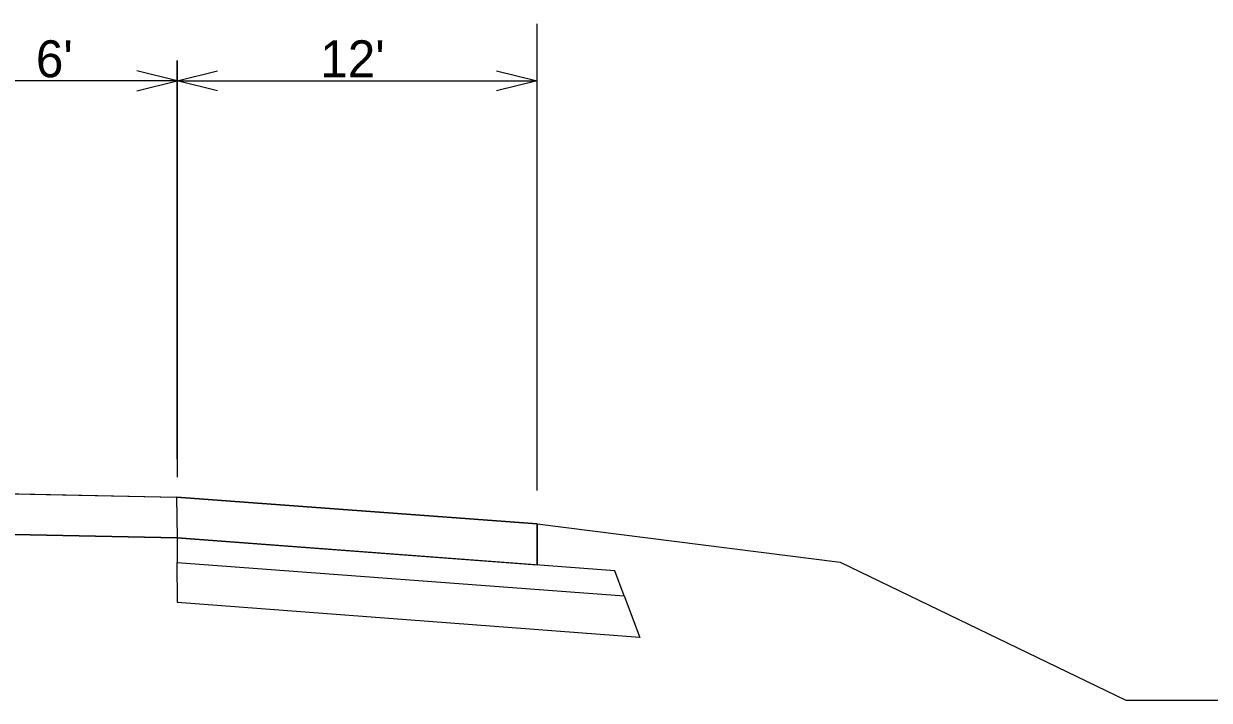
# Model space of a CAD drawing. Extents: x 10133 to 81668, y 4856 to 11018.
# Drawn here: x 11836.4 to 12317.7, y 8656.6 to 8931.3 of the extents above; entities that cross this region are included whole.
import ezdxf

# ---------------------------------------------------------------- set-up
doc = ezdxf.new("R2010")
doc.units = 0
for name, color, linetype in [('dsnStdDimension', 7, 'Continuous'), ('dsnXsPCCPavementBottom', 7, 'Continuous'), ('dsnXsShldrEarthFill', 7, 'Continuous'), ('dsnXsShldrGranular', 7, 'Continuous'), ('dsnXsShldrGranularBottom', 7, 'Continuous'), ('dsnXsShldrSpecialBackBottom', 7, 'Continuous')]:
    doc.layers.add(name, color=color, linetype=linetype)

msp = doc.modelspace()

# ---------------------------------------------------------------- linework, layer by layer
at = {"layer": 'dsnStdDimension'}
for p, q in [((12076.34, 8709.14), (11898.67, 8722.47)), ((11898.67, 8712.57), (12080.17, 8698.96)), ((12080.17, 8698.96), (12076.34, 8709.14))]:
    msp.add_line(p, q, dxfattribs=at)
msp.add_lwpolyline([(11898.67, 8722.47), (11898.67, 8722.47), (11898.67, 8712.57), (11898.67, 8712.57)], dxfattribs=at)
msp.add_lwpolyline([(11898.67, 8712.57), (11898.67, 8712.57), (12080.17, 8698.96), (12086.53, 8682.08), (11898.78, 8696.25), (11898.78, 8696.25)], close=True, dxfattribs=at)
at = {"layer": 'dsnXsPCCPavementBottom'}
for p, q in [((12044.78, 8741.68), (12044.78, 8931.28)), ((11898.67, 8754.52), (11898.67, 8916.39)), ((11898.67, 8916.39), (11898.67, 8754.52)), ((11898.67, 8916.39), (11898.67, 8754.52)), ((11898.67, 8754.52), (11898.67, 8916.39)), ((11898.67, 8916.39), (11898.67, 8747.22)), ((11898.67, 8908.07), (11800.5, 8908.07)), ((11898.67, 8908.07), (12044.78, 8908.07))]:
    msp.add_line(p, q, dxfattribs=at)
for points in [[(11882.28, 8903.97), (11898.67, 8908.07), (11882.28, 8912.17)], [(11915.06, 8903.97), (11898.67, 8908.07), (11915.06, 8912.17)], [(12028.39, 8912.17), (12044.78, 8908.07), (12028.39, 8903.97)]]:
    msp.add_lwpolyline(points, dxfattribs=at)
at = {"layer": 'dsnXsShldrGranular'}
msp.add_line((11898.67, 8722.47), (11699.65, 8726.7), dxfattribs=at)
msp.add_lwpolyline([(11700, 8743.25), (11898.43, 8739.03), (11898.67, 8722.47)], dxfattribs=at)
msp.add_lwpolyline([(12044.78, 8728.14), (11898.43, 8739.03), (11898.67, 8722.47), (12044.78, 8711.51)], close=True, dxfattribs=at)
at = {"layer": 'dsnXsShldrGranularBottom'}
for p, q in [((11700, 8743.25), (11898.43, 8739.03)), ((11898.43, 8739.03), (11898.67, 8722.47)), ((11898.43, 8739.03), (11898.67, 8722.47)), ((11898.43, 8739.03), (11898.67, 8722.47)), ((11898.43, 8739.03), (11898.67, 8722.47)), ((12044.78, 8728.14), (12167.89, 8712.67)), ((11699.65, 8726.7), (11898.67, 8722.47)), ((12167.89, 8712.67), (12283.88, 8656.55)), ((12283.88, 8656.55), (12449.44, 8656.55))]:
    msp.add_line(p, q, dxfattribs=at)
at = {"layer": 'dsnXsShldrSpecialBackBottom'}
for p, q in [((11898.43, 8739.03), (12044.78, 8728.14)), ((12044.78, 8728.14), (12044.78, 8711.51)), ((11898.67, 8722.47), (12044.78, 8711.51))]:
    msp.add_line(p, q, dxfattribs=at)

# ---------------------------------------------------------------- texts
at = {"layer": 'dsnXsShldrEarthFill'}
msp.add_text("6'", height=15, dxfattribs=at).set_placement((11841.31, 8909.53))
msp.add_text("12'", height=15, rotation=0, dxfattribs=at).set_placement((11956.8, 8909.53))

doc.saveas('drawing.dxf')
